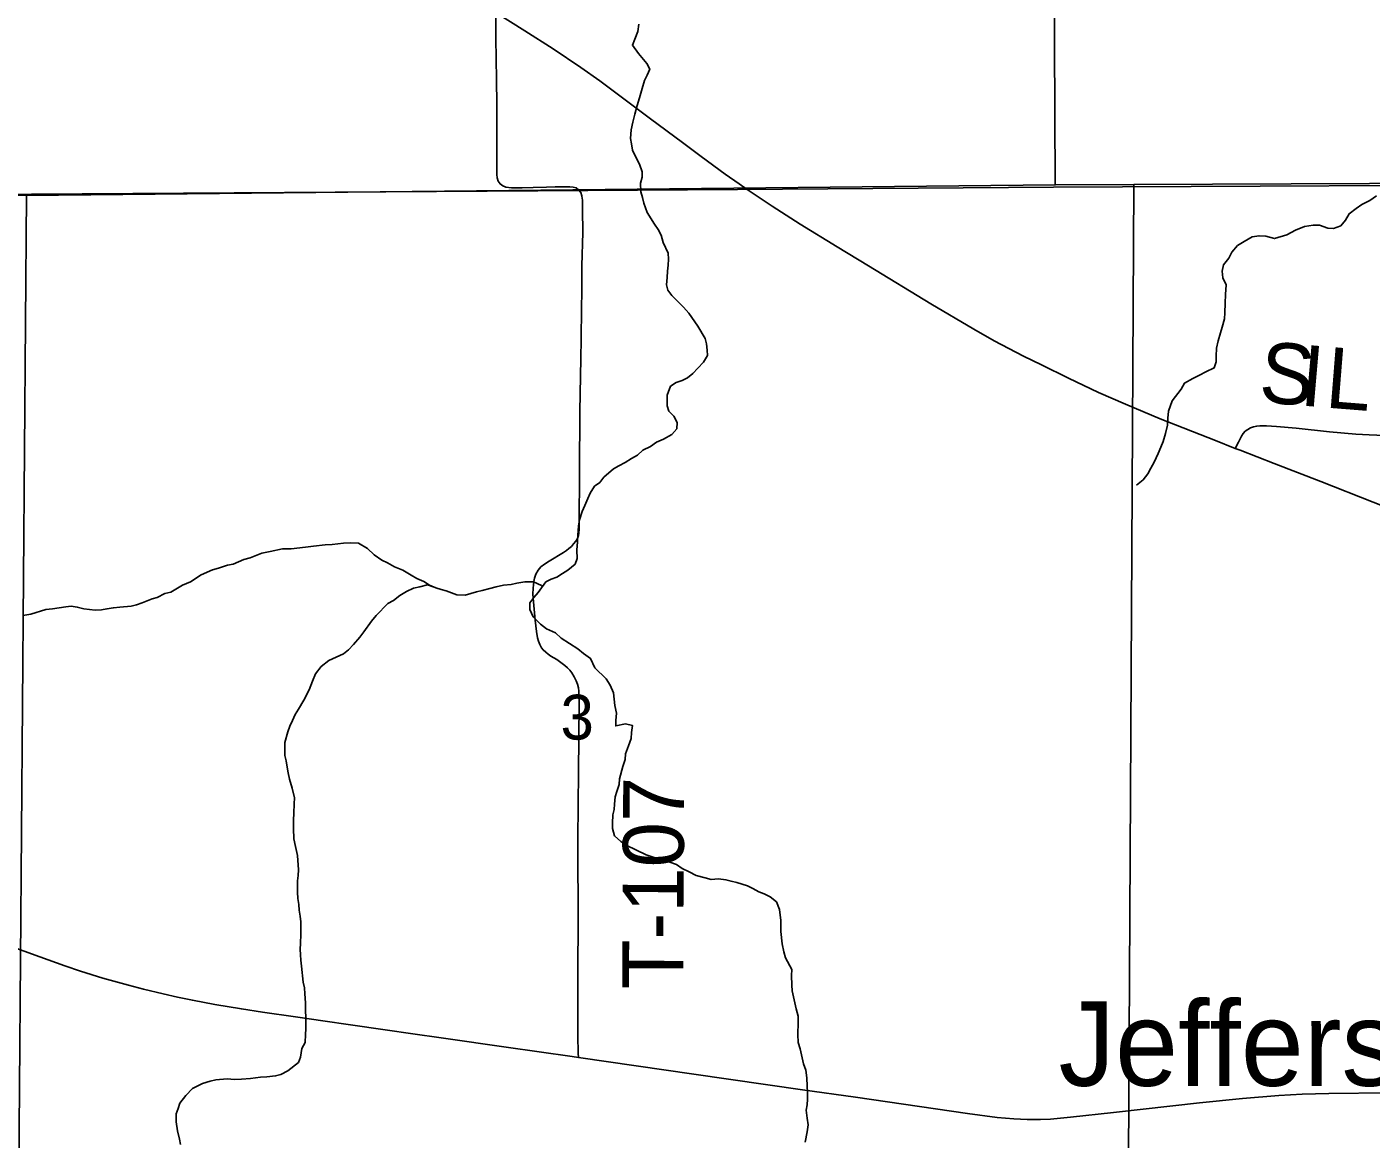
# Model space of a CAD drawing. Extents: x 1985906 to 2360102, y 891258 to 1222054.
# Drawn here: x 2092575 to 2099202, y 1020711 to 1026196 of the extents above; entities that cross this region are included whole.
import ezdxf

# ---------------------------------------------------------------- set-up
doc = ezdxf.new("R2010")
doc.units = 0
for name, color, linetype in [('GM_X_County_Road', 7, 'Continuous'), ('GM_X_Minor_River', 7, 'Continuous'), ('GM_X_Section', 7, 'Continuous'), ('GM_X_Section_Text', 7, 'Continuous'), ('GM_X_Township', 7, 'Continuous'), ('GM_X_Township_Road', 7, 'Continuous'), ('GM_X_Township_Road_Text', 7, 'Continuous'), ('GM_X_Unincorporated_Text', 7, 'Continuous'), ('GM_X_US_Route', 7, 'Continuous')]:
    doc.layers.add(name, color=color, linetype=linetype)

msp = doc.modelspace()

# ---------------------------------------------------------------- linework, layer by layer
at = {"layer": 'GM_X_County_Road'}
for points in [[(2092485.2, 1021666.5), (2092638.9, 1021609.6), (2092762.3, 1021565), (2092840.2, 1021538.7), (2092950.1, 1021505.1), (2093076.8, 1021470.3), (2093150.6, 1021450.9), (2093247, 1021428.3), (2093318.2, 1021411.8), (2093391.2, 1021396.1), (2093502.3, 1021375.3), (2093632.5, 1021353.5), (2093736.4, 1021337.6), (2093898.8, 1021314), (2094045, 1021293.5), (2094158.6, 1021277), (2094353.3, 1021248.5), (2094467, 1021232), (2094629.4, 1021208.9), (2094938, 1021165.1), (2095262.8, 1021118.1), (2095293.9, 1021113.6)], [(2095293.9, 1021113.6), (2095863.7, 1021031.8), (2096399.5, 1020954.3), (2096659.6, 1020917.9), (2097211.6, 1020838), (2097358.1, 1020818.2), (2097440, 1020810.8), (2097505.8, 1020807.6), (2097571.7, 1020807.6), (2097621, 1020809.9), (2097719.2, 1020819.1), (2097931.3, 1020842.7), (2098355.2, 1020890.1), (2098567.3, 1020911.9), (2098747, 1020926.7), (2098861.6, 1020933.2), (2098992.7, 1020936.9), (2099287.9, 1020940.1), (2099517.5, 1020940.7), (2099796.3, 1020941.4), (2099938.7, 1020942)]]:
    msp.add_lwpolyline(points, dxfattribs=at)
at = {"layer": 'GM_X_Minor_River'}
for points in [[(2095592.1, 1026210.2), (2095586.2, 1026174), (2095572.4, 1026135.8), (2095560.6, 1026105.7), (2095590.8, 1026065.7), (2095631.2, 1026015.7), (2095645.3, 1025987.6), (2095633.5, 1025957.4), (2095619.6, 1025931.3), (2095607.8, 1025893.1), (2095596, 1025846.9), (2095584.1, 1025808.7), (2095572.3, 1025766.5), (2095562.5, 1025726.3), (2095554.7, 1025688.1), (2095550.9, 1025645.9), (2095555.1, 1025619.8), (2095561.2, 1025587.8), (2095573.4, 1025559.7), (2095595.7, 1025519.7), (2095607.9, 1025481.6), (2095608, 1025455.5), (2095600.2, 1025425.3), (2095602.4, 1025383.2), (2095610.6, 1025355.1), (2095616.7, 1025327), (2095633, 1025280.9), (2095669.4, 1025222.9), (2095687.5, 1025196.9), (2095701.7, 1025168.8), (2095711.9, 1025132.8), (2095736.2, 1025080.7)], [(2099227.5, 1025363.6), (2099195.6, 1025339.4), (2099155.6, 1025321.1), (2099127.6, 1025300.9), (2099093.7, 1025274.7), (2099075.8, 1025242.5), (2099051.9, 1025214.3), (2099015.9, 1025202), (2098987.9, 1025203.9), (2098947.7, 1025217.8), (2098915.7, 1025217.7), (2098873.6, 1025211.4), (2098829.6, 1025193.2), (2098785.7, 1025170.9), (2098725.6, 1025152.5), (2098683.5, 1025164.4), (2098649.4, 1025166.2), (2098615.4, 1025160.1), (2098575.4, 1025137.8), (2098543.5, 1025117.6), (2098515.6, 1025085.3), (2098499.7, 1025055.2), (2098473.8, 1025022.9), (2098468, 1024990.8), (2098470.1, 1024958.7), (2098486.4, 1024924.6), (2098484.6, 1024876.4), (2098482.8, 1024834.3), (2098481.1, 1024786.1), (2098479.2, 1024756), (2098467.4, 1024715.8), (2098459.5, 1024687.6), (2098447.7, 1024647.4), (2098439.9, 1024611.2), (2098438.1, 1024573.1), (2098438.2, 1024545), (2098428.4, 1024514.8), (2098386.4, 1024494.6), (2098356.4, 1024478.4), (2098322.4, 1024462.2), (2098282.5, 1024439.9), (2098264.6, 1024409.7), (2098220.8, 1024351.3), (2098203.1, 1024301), (2098199.2, 1024266.9), (2098197.4, 1024232.7), (2098187.6, 1024190.5), (2098175.8, 1024152.3), (2098165.9, 1024124.2), (2098152, 1024092), (2098132.2, 1024049.8), (2098116.3, 1024019.6), (2098100.5, 1023991.4), (2098078.6, 1023963.2), (2098044.6, 1023936.9)], [(2095736.2, 1025080.7), (2095738.4, 1025050.6), (2095736.5, 1025020.4), (2095732.7, 1024992.3), (2095730.8, 1024960.2), (2095729, 1024924.1), (2095735.2, 1024898), (2095755.3, 1024872), (2095783.6, 1024842), (2095811.8, 1024814), (2095838, 1024784), (2095882.4, 1024720), (2095918.8, 1024659.9), (2095924.9, 1024633.9), (2095929.1, 1024601.8), (2095931.2, 1024575.7), (2095911.4, 1024543.5), (2095883.5, 1024513.2), (2095857.5, 1024487), (2095831.6, 1024464.8), (2095805.6, 1024452.7), (2095775.6, 1024442.5), (2095747.7, 1024424.3), (2095731.9, 1024380), (2095732.1, 1024327.9), (2095740.3, 1024301.8), (2095764.5, 1024275.8), (2095780.6, 1024245.8), (2095778.8, 1024213.7), (2095754.9, 1024185.4), (2095712.9, 1024163.2), (2095679, 1024149), (2095649, 1024126.7), (2095611, 1024108.5), (2095585.1, 1024084.3), (2095555.1, 1024068.1), (2095525.2, 1024047.9), (2095493.2, 1024031.7), (2095467.2, 1024017.5), (2095419.4, 1023975.1), (2095399.5, 1023948.9), (2095373.5, 1023930.8), (2095351.6, 1023896.5), (2095339.8, 1023870.4), (2095325.9, 1023836.2), (2095312, 1023806), (2095300.2, 1023765.8), (2095294.4, 1023735.7), (2095290.6, 1023689.5), (2095288.8, 1023657.4), (2095287, 1023615.2), (2095287.2, 1023575.1), (2095277.3, 1023546.9), (2095241.4, 1023516.6), (2095215.4, 1023500.4), (2095187.5, 1023482.3), (2095159.5, 1023472.1), (2095133.5, 1023459.9), (2095095.7, 1023407.6), (2095073.8, 1023381.4), (2095053.9, 1023355.2), (2095054, 1023323.1), (2095070.3, 1023287), (2095106.5, 1023251), (2095136.7, 1023227.1), (2095180.9, 1023207.2), (2095209.1, 1023181.2), (2095291.5, 1023129.4), (2095319.7, 1023105.5), (2095353.9, 1023081.5), (2095374.2, 1023035.4), (2095430.5, 1022981.5), (2095450.8, 1022949.5), (2095467, 1022911.4), (2095471.1, 1022881.3), (2095473.3, 1022849.2), (2095481.5, 1022811.1), (2095477.7, 1022775), (2095477.9, 1022748.9), (2095525.9, 1022759.1), (2095560, 1022751.2), (2095556.2, 1022717.1), (2095554.3, 1022687), (2095540.5, 1022650.8), (2095526.7, 1022610.6), (2095524.8, 1022582.5), (2095513, 1022548.3), (2095497.2, 1022488), (2095495.4, 1022459.9), (2095483.6, 1022425.7), (2095475.7, 1022399.6), (2095471.8, 1022363.4), (2095470, 1022337.3), (2095464.1, 1022311.2), (2095462.3, 1022269), (2095462.5, 1022242.9), (2095472.7, 1022206.8), (2095502.9, 1022178.9), (2095533, 1022158.9), (2095577.2, 1022137), (2095627.5, 1022113.2)], [(2095116.1, 1023435.9), (2095111.5, 1023441.8), (2095073.4, 1023459.7), (2095029.3, 1023459.4), (2094991.2, 1023453.3), (2094963.2, 1023447.1), (2094925.2, 1023442.9), (2094889.1, 1023434.7), (2094857.1, 1023426.5), (2094819.1, 1023416.3), (2094791.1, 1023410.2), (2094735.1, 1023393.9), (2094695, 1023395.7), (2094642.8, 1023415.5), (2094616.7, 1023421.4), (2094590.6, 1023429.3), (2094560.5, 1023443.3), (2094532.3, 1023461.2), (2094498.2, 1023475.1), (2094470, 1023493), (2094427.8, 1023516.9), (2094387.7, 1023532.8), (2094353.5, 1023552.7), (2094325.4, 1023566.6), (2094287.2, 1023592.6), (2094254.9, 1023624.5), (2094210.7, 1023650.4), (2094168.6, 1023652.2), (2094136.6, 1023650.1), (2094080.5, 1023643.8), (2094046.4, 1023641.7), (2093988.3, 1023635.4), (2093948.3, 1023631.2), (2093878.2, 1023622.8), (2093836.1, 1023622.6), (2093774.1, 1023608.3), (2093734, 1023600.1), (2093676, 1023577.7), (2093644, 1023569.6), (2093592, 1023547.2), (2093564, 1023541.1), (2093520, 1023526.8), (2093490, 1023518.7), (2093434, 1023494.3), (2093382.1, 1023460), (2093342.1, 1023443.7), (2093284.2, 1023409.3), (2093256.1, 1023401.2), (2093218.2, 1023382.9), (2093192.2, 1023374.8), (2093144.2, 1023356.5), (2093116.2, 1023346.3), (2093090.1, 1023340.2), (2093034.1, 1023333.9), (2093002, 1023331.8), (2092970, 1023325.6), (2092943.9, 1023321.4), (2092911.9, 1023319.3), (2092883.8, 1023323.2), (2092855.8, 1023327.1), (2092823.6, 1023334.9), (2092793.6, 1023338.8), (2092767.5, 1023336.7), (2092701.4, 1023326.4), (2092669.4, 1023322.2), (2092595.4, 1023299.8), (2092555.3, 1023293.6)], [(2094582.5, 1023433.1), (2094550.4, 1023445.2), (2094512.4, 1023435), (2094480.4, 1023428.8), (2094446.4, 1023412.6), (2094414.4, 1023392.4), (2094382.5, 1023368.2), (2094354.5, 1023352), (2094296.7, 1023293.5), (2094274.8, 1023265.3), (2094237, 1023212.9), (2094217.1, 1023186.7), (2094185.3, 1023150.5), (2094161.3, 1023124.3), (2094135.4, 1023104.1), (2094063.4, 1023071.6), (2094025.5, 1023041.3), (2093997.6, 1023005.1), (2093983.8, 1022968.9), (2093966, 1022926.6), (2093940.2, 1022876.3), (2093914.4, 1022832.1), (2093898.5, 1022805.9), (2093884.6, 1022775.7), (2093870.7, 1022747.5), (2093860.9, 1022719.4), (2093847.1, 1022667.1), (2093847.3, 1022633), (2093847.5, 1022602.9), (2093853.6, 1022576.8), (2093857.8, 1022544.7), (2093863.9, 1022516.7), (2093870.1, 1022486.6), (2093882.4, 1022442.5), (2093894.6, 1022394.3), (2093892.8, 1022364.2), (2093891, 1022318), (2093889.2, 1022283.9), (2093889.4, 1022243.8), (2093891.7, 1022191.6), (2093899.9, 1022153.5), (2093910.1, 1022109.4), (2093914.5, 1022039.1), (2093912.7, 1022011), (2093908.8, 1021984.9), (2093909.1, 1021928.7), (2093911.2, 1021898.6), (2093915.4, 1021868.5), (2093917.6, 1021840.4), (2093921.7, 1021810.3), (2093925.9, 1021782.2), (2093926.2, 1021722), (2093924.4, 1021675.8), (2093922.6, 1021647.7), (2093924.7, 1021619.6), (2093924.9, 1021593.5), (2093929, 1021563.4), (2093937.5, 1021485.2), (2093943.6, 1021457.1), (2093945.8, 1021427), (2093948, 1021382.8), (2093948.2, 1021350.7), (2093950.4, 1021306.6), (2093950.7, 1021254.4), (2093948.8, 1021226.3), (2093947, 1021188.1), (2093931.2, 1021157.9), (2093923.4, 1021115.7), (2093913.5, 1021089.6), (2093861.6, 1021047.2), (2093827.6, 1021029), (2093801.6, 1021022.8), (2093757.5, 1021018.6), (2093727.5, 1021016.5), (2093677.4, 1021010.2), (2093633.4, 1021006), (2093599.3, 1021005.8), (2093563.2, 1021007.7), (2093507.1, 1021003.4), (2093479.1, 1020997.3), (2093441.1, 1020985), (2093391.1, 1020960.7), (2093359.2, 1020926.5), (2093329.4, 1020888.2), (2093321.5, 1020862), (2093311.6, 1020835.9), (2093311.8, 1020795.8), (2093318.1, 1020751.6), (2093328.3, 1020711.5), (2093332.5, 1020685.4)], [(2095627.5, 1022113.2), (2095653.5, 1022105.3), (2095685.7, 1022093.4), (2095711.8, 1022085.5), (2095743.9, 1022077.6), (2095778, 1022065.7), (2095806.1, 1022045.8), (2095840.3, 1022029.8), (2095874.5, 1022011.9), (2095918.6, 1022000.1), (2095948.7, 1021992.2), (2095984.8, 1021994.4), (2096020.9, 1021990.5), (2096047, 1021982.6), (2096075, 1021976.7), (2096127.2, 1021960.9), (2096153.3, 1021947), (2096183.5, 1021931), (2096209.6, 1021921.1), (2096239.7, 1021905.2), (2096269.9, 1021881.3), (2096286.1, 1021843.2), (2096292.4, 1021789), (2096292.7, 1021734.8), (2096299, 1021674.6), (2096307.3, 1021634.5), (2096315.4, 1021604.4), (2096345.8, 1021548.4), (2096343.9, 1021518.2), (2096346.2, 1021470.1), (2096348.3, 1021442), (2096366.8, 1021353.7), (2096377.1, 1021317.7), (2096377.2, 1021285.5), (2096375.5, 1021227.3), (2096377.7, 1021187.2), (2096387.9, 1021157.1), (2096404.3, 1021082.9), (2096414.5, 1021050.8), (2096420.7, 1021012.7), (2096420.9, 1020972.6), (2096423.1, 1020942.5), (2096423.3, 1020908.3), (2096421.4, 1020880.2), (2096417.5, 1020854.1), (2096421.8, 1020814), (2096425.9, 1020781.9), (2096422.1, 1020747.7), (2096412.4, 1020695.5)]]:
    msp.add_lwpolyline(points, dxfattribs=at)
at = {"layer": 'GM_X_Section'}
for points in [[(2097619, 1030699.6), (2097644.6, 1025416.7), (2092573.9, 1025364), (2092101.6, 1025365.7), (2092077.6, 1030712.7)], [(2103026, 1030725.8), (2103067.7, 1025441), (2098032.8, 1025418.6), (2097644.6, 1025416.7), (2097619, 1030699.6)], [(2103067.7, 1025441), (2103217.8, 1025431.7), (2103278.8, 1020259), (2098003.5, 1020315.5), (2098032.8, 1025418.6)], [(2097644.6, 1025416.7), (2098032.8, 1025418.6), (2098003.5, 1020315.5), (2092534.2, 1020341), (2092573.9, 1025364)]]:
    msp.add_lwpolyline(points, close=True, dxfattribs=at)
at = {"layer": 'GM_X_Township'}
for points in [[(2108590.2, 1057156.5), (2108639.5, 1052043.3), (2108637.1, 1049741.1), (2108630.4, 1047484.6), (2108627.5, 1046838.9), (2108612.5, 1046641.2), (2108630.4, 1044190.7), (2108630.3, 1044082.6), (2108629.3, 1041511.6), (2108630.8, 1034179.2), (2108627, 1033545.8), (2108551.5, 1029433), (2108528.9, 1027031.5), (2108514.5, 1025497.4), (2103772.2, 1025425.9), (2103219.4, 1025417.6), (2103068.8, 1025432.7), (2097635.3, 1025405.6), (2096078.3, 1025395), (2095094.6, 1025388.3), (2092097.4, 1025367.8)], [(2092097.4, 1025367.8), (2095094.6, 1025388.3), (2096078.3, 1025395), (2097635.3, 1025405.6), (2103068.8, 1025432.7), (2103219.4, 1025417.6), (2103772.2, 1025425.9), (2108514.5, 1025497.4), (2108514.7, 1024273), (2108515.5, 1020728.6), (2108516.1, 1018164.4), (2108516.1, 1017976.2), (2108516.2, 1017490.1), (2108516.8, 1014917.1), (2108517.3, 1014690.8), (2108496.3, 1012312.2), (2108481.1, 1010602), (2108488.7, 1009238.5)]]:
    msp.add_lwpolyline(points, dxfattribs=at)
at = {"layer": 'GM_X_Township_Road'}
for points in [[(2094932.2, 1025407.1), (2094920.8, 1025412.1), (2094908.1, 1025421.8), (2094898.5, 1025434.6), (2094893.3, 1025452), (2094892.3, 1025468.1), (2094891.4, 1025494.5), (2094891.4, 1025524.8), (2094892.3, 1025592.9), (2094891.4, 1025813.2), (2094890.5, 1025937.1), (2094887.7, 1026140.3), (2094887.7, 1026237.7), (2094887.9, 1026265.3)], [(2095282.8, 1025401.8), (2095267.7, 1025406.5), (2095252.5, 1025407.5), (2095239.3, 1025407.5), (2095224.2, 1025407.5), (2095207.2, 1025407.5), (2095179.7, 1025407.5), (2095137.2, 1025405.6), (2095071, 1025404.7), (2095017.1, 1025401.9), (2094964.1, 1025401.9), (2094935.7, 1025405.6), (2094932.2, 1025407.1)], [(2095293.9, 1021113.6), (2095293.4, 1021135.6), (2095291.5, 1021219.7), (2095291.5, 1021349.2), (2095291.6, 1021548.7), (2095292.6, 1021777.5), (2095291, 1022167.2), (2095292.7, 1022381.7), (2095294.6, 1022500), (2095296.5, 1022711.7), (2095297.5, 1022841.3), (2095297.5, 1022888.6), (2095296.9, 1022920.8), (2095294.5, 1022936.9), (2095289.9, 1022954.7), (2095283.3, 1022971.8), (2095273.9, 1022991.6), (2095262, 1023010.7), (2095251.2, 1023023.8), (2095240.1, 1023035), (2095226.6, 1023047.4), (2095186.9, 1023075.8), (2095158.8, 1023093), (2095145.6, 1023102.7), (2095133.3, 1023113.1), (2095119.8, 1023124), (2095111.3, 1023134.4), (2095103.7, 1023149.6), (2095097.1, 1023166.6), (2095092.4, 1023183.6), (2095088.1, 1023214.8), (2095081, 1023270.6), (2095071.9, 1023361.5), (2095069.7, 1023398.2), (2095070.6, 1023427.5), (2095074.5, 1023460.6), (2095077.3, 1023477.7), (2095083.9, 1023497.5), (2095095.3, 1023517.4), (2095109.4, 1023533.5), (2095126.5, 1023545.8), (2095150.3, 1023561.7), (2095221, 1023604.3), (2095234.7, 1023613.4), (2095247.5, 1023623.6), (2095259.6, 1023634.5), (2095269.9, 1023647.1), (2095280.6, 1023659.2), (2095289.1, 1023673.4), (2095293.8, 1023687.6), (2095296.7, 1023698.9), (2095297.6, 1023720.6), (2095297.6, 1023755.6), (2095297.6, 1023822.8), (2095298.6, 1023921.1), (2095298.6, 1024021.3), (2095299.6, 1024103.6), (2095300.6, 1024201), (2095301.5, 1024300.2), (2095306.3, 1024561.2), (2095307.5, 1024656.9), (2095309.2, 1024808), (2095310.1, 1024893.1), (2095311.1, 1025017.6), (2095315.2, 1025181.7), (2095314.9, 1025295), (2095314.9, 1025332.8), (2095313.8, 1025343.4), (2095313.1, 1025349.8), (2095311.2, 1025363), (2095305.5, 1025379.1), (2095294.1, 1025393.3), (2095282.8, 1025401.8)], [(2098532.1, 1024117.6), (2098547.7, 1024148.8), (2098562.2, 1024177.5), (2098571, 1024190.6), (2098581.4, 1024202.1), (2098593.8, 1024211.3), (2098607.5, 1024218.7), (2098622.3, 1024223.9), (2098637.8, 1024227.3), (2098653.7, 1024229.1), (2098686, 1024229.6), (2098735, 1024226.3), (2098833, 1024216.9), (2098996.3, 1024199.5), (2099126.6, 1024187.7), (2099191.8, 1024183.8), (2099306.8, 1024179.7)]]:
    msp.add_lwpolyline(points, dxfattribs=at)
at = {"layer": 'GM_X_US_Route'}
for points in [[(2094887.9, 1026265.3), (2095030.7, 1026177), (2095170.4, 1026087.8), (2095306.5, 1025996.4), (2095399.7, 1025929.5), (2095531.4, 1025831.7), (2095649.6, 1025743.3), (2095807.3, 1025625.6), (2095898.9, 1025557.1), (2096017.5, 1025470.6), (2096085.9, 1025422.7), (2096126.2, 1025394.3), (2096248.8, 1025311.8), (2096387.3, 1025223.6), (2096569.1, 1025111.7), (2096723.4, 1025018.4), (2097031.1, 1024830.1), (2097243.4, 1024704.7), (2097343.6, 1024648.3), (2097488.8, 1024571.7), (2097576.1, 1024528.9)], [(2097576.1, 1024528.9), (2097710, 1024463.4), (2097858.1, 1024393.1), (2097991.2, 1024334.9), (2098161.1, 1024263.7), (2098434.9, 1024155.8), (2098532.1, 1024117.6), (2098555.8, 1024108.3), (2098724.1, 1024043.3), (2098953.6, 1023954.4), (2099469.3, 1023750.9)]]:
    msp.add_lwpolyline(points, dxfattribs=at)

# ---------------------------------------------------------------- texts
at = {"layer": 'GM_X_Section_Text'}
msp.add_text('3', height=221, rotation=0.00001, dxfattribs=at).set_placement((2095205.8, 1022681.6))
at = {"layer": 'GM_X_Township_Road_Text'}
for s, rotation, p in [('S', 355.03808, (2098643.3, 1024347.7)), ('I', 355.05169, (2098845, 1024330.2)), ('L', 355.46029, (2098970.1, 1024319.4)), ('T-107', 89.72774, (2095810.1, 1021448.9))]:
    msp.add_text(s, height=300, rotation=rotation, dxfattribs=at).set_placement(p)
at = {"layer": 'GM_X_Unincorporated_Text'}
msp.add_text('Jefferson', height=417, rotation=0.00001, dxfattribs=at).set_placement((2097661, 1020973.9))

doc.saveas('drawing.dxf')
